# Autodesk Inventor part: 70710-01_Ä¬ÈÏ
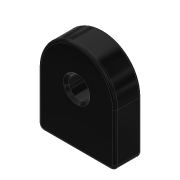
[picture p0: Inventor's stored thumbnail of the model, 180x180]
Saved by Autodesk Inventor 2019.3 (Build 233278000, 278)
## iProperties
Created: 2010-06
Part Number: 70710-01_Ä¬ÈÏ
Material: Ogólny
Document SubType Name: Modeling
Designer: CADENGINEERING4
Density: 1 g/cm^3
Appearance: Gładki — czarny
Author: CADENGINEERING4
Revision Number: ÈÎºÎ
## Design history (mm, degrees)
feature "NONE"
node "Bryła1"
